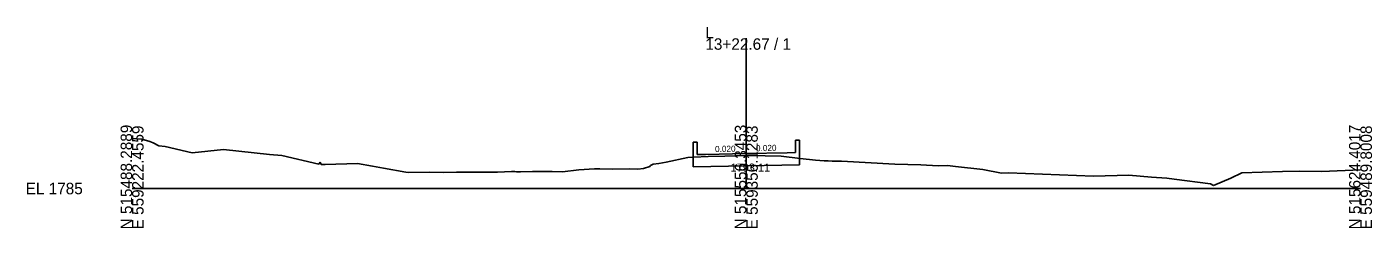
# Model space of a CAD drawing. Extents: x -26 to 1303, y -10 to 9545.
# Drawn here: x -25.7 to 302.8, y 8490.3 to 8539.5 of the extents above; entities that cross this region are included whole.
import ezdxf

# ---------------------------------------------------------------- set-up
doc = ezdxf.new("R2010")
doc.units = 0
for name, color, linetype in [('Exist Cross Section Cell', 7, 'Continuous'), ('Exist XS Center Line Elevation Label', 7, 'Continuous'), ('Exist XS Ground Line', 7, 'Continuous'), ('Prop XS Bridge', 7, 'Continuous'), ('Prop XS Dump Level', 7, 'Continuous'), ('Prop XS SE Text', 7, 'Continuous')]:
    doc.layers.add(name, color=color, linetype=linetype)

msp = doc.modelspace()

# ---------------------------------------------------------------- linework, layer by layer
at = {"layer": 'Exist Cross Section Cell'}
for p, q in [((150, 8500), (150, 8536.74)), ((0, 8500), (150, 8500)), ((150, 8500), (300, 8500))]:
    msp.add_line(p, q, dxfattribs=at)
at = {"layer": 'Exist XS Ground Line'}
for p, q in [((0, 8512.25), (2.41, 8512.03)), ((2.41, 8512.03), (4.35, 8511.48)), ((4.35, 8511.48), (5.13, 8511.21)), ((5.13, 8511.21), (6.55, 8510.43)), ((6.55, 8510.43), (8.05, 8510.29)), ((8.05, 8510.29), (14.68, 8508.74)), ((14.68, 8508.74), (22.32, 8509.58)), ((22.32, 8509.58), (33.55, 8508.35)), ((33.55, 8508.35), (36.54, 8508.07)), ((36.54, 8508.07), (45.58, 8505.94)), ((45.58, 8505.94), (45.93, 8506.47)), ((45.93, 8506.47), (46.2, 8505.85)), ((46.2, 8505.85), (47.14, 8505.87)), ((47.14, 8505.87), (55.06, 8506.08)), ((55.06, 8506.08), (58.68, 8505.44)), ((126.59, 8505.6), (127.27, 8505.94)), ((127.27, 8505.94), (128.66, 8506.15)), ((128.66, 8506.15), (130.46, 8506.41)), ((130.46, 8506.41), (135.7, 8507.58)), ((135.7, 8507.58), (137.21, 8507.69)), ((137.21, 8507.69), (140.72, 8507.79)), ((140.72, 8507.79), (144.78, 8507.89)), ((144.78, 8507.89), (149.88, 8508.11)), ((149.88, 8508.11), (154.62, 8507.99)), ((154.62, 8507.99), (158.51, 8507.88)), ((158.51, 8507.88), (163.14, 8507.36)), ((163.14, 8507.36), (166.87, 8506.97)), ((166.87, 8506.97), (169.01, 8506.76)), ((169.01, 8506.76), (170.01, 8506.77)), ((170.01, 8506.77), (170.95, 8506.7)), ((170.95, 8506.7), (173.23, 8506.7)), ((173.23, 8506.7), (186.27, 8505.98)), ((186.27, 8505.98), (189.48, 8505.84)), ((189.48, 8505.84), (192.63, 8505.81)), ((192.63, 8505.81), (196.87, 8505.55)), ((58.68, 8505.44), (61.38, 8504.95)), ((61.38, 8504.95), (66.86, 8504)), ((66.86, 8504), (67.46, 8503.88)), ((67.46, 8503.88), (72.73, 8504.02)), ((72.73, 8504.02), (76.08, 8503.94)), ((76.08, 8503.94), (79.2, 8504.01)), ((79.2, 8504.01), (80.99, 8503.99)), ((80.99, 8503.99), (88.29, 8503.99)), ((88.29, 8503.99), (89.23, 8503.98)), ((89.23, 8503.98), (92.67, 8504.14)), ((92.67, 8504.14), (93.45, 8504.13)), ((93.45, 8504.13), (93.87, 8504.12)), ((93.87, 8504.12), (94.89, 8504.11)), ((94.89, 8504.11), (97.81, 8504.14)), ((97.81, 8504.14), (102.55, 8504.15)), ((102.55, 8504.15), (105.08, 8504.07)), ((105.08, 8504.07), (109.1, 8504.55)), ((109.1, 8504.55), (112.96, 8504.78)), ((112.96, 8504.78), (114.25, 8504.8)), ((114.25, 8504.8), (117.33, 8504.75)), ((117.33, 8504.75), (121.41, 8504.79)), ((121.41, 8504.79), (123.51, 8504.73)), ((123.51, 8504.73), (124.93, 8504.86)), ((124.93, 8504.86), (126.46, 8505.4)), ((126.46, 8505.4), (126.59, 8505.6)), ((196.87, 8505.55), (199.12, 8505.61)), ((199.12, 8505.61), (201.08, 8505.42)), ((201.08, 8505.42), (207.77, 8504.66)), ((207.77, 8504.66), (212.29, 8503.77)), ((212.29, 8503.77), (214.04, 8503.83)), ((214.04, 8503.83), (234.82, 8503.04)), ((234.82, 8503.04), (243.42, 8503.28)), ((243.42, 8503.28), (249, 8502.8)), ((249, 8502.8), (252.7, 8502.53)), ((252.7, 8502.53), (254.52, 8502.25)), ((264.07, 8500.71), (268.34, 8502.49)), ((268.34, 8502.49), (271.05, 8503.8)), ((271.05, 8503.8), (280.92, 8504.14)), ((280.92, 8504.14), (285.18, 8504.21)), ((285.18, 8504.21), (290.6, 8504.19)), ((290.6, 8504.19), (300, 8504.55)), ((254.52, 8502.25), (263.39, 8501.14)), ((263.39, 8501.14), (264.07, 8500.71))]:
    msp.add_line(p, q, dxfattribs=at)
at = {"layer": 'Prop XS Bridge'}
for p, q in [((137, 8511.32), (137, 8508.32)), ((138, 8511.32), (137, 8511.32)), ((138, 8508.32), (138, 8511.32)), ((162, 8508.8), (162, 8511.8)), ((162, 8511.8), (163, 8511.8)), ((163, 8511.8), (163, 8508.8)), ((137, 8508.32), (137, 8505.32)), ((163, 8505.8), (137, 8505.32)), ((140, 8508.36), (138, 8508.32)), ((140, 8508.36), (150, 8508.56)), ((150, 8508.56), (160, 8508.76)), ((160, 8508.76), (162, 8508.8)), ((163, 8508.8), (163, 8505.8))]:
    msp.add_line(p, q, dxfattribs=at)
at = {"layer": 'Prop XS Dump Level'}
for p, q in [((140, 8508.36), (150, 8508.56)), ((150, 8508.56), (160, 8508.76))]:
    msp.add_line(p, q, dxfattribs=at)

# ---------------------------------------------------------------- texts
at = {"layer": 'Exist Cross Section Cell'}
for s, p in [('L', (140, 8536.74)), ('13+22.67 / 1', (140, 8533.94)), ('EL 1785', (-26, 8498.6))]:
    msp.add_text(s, height=2.8, dxfattribs=at).set_placement(p)
for s, p in [('N 515488.2889', (0, 8490)), ('E 559222.4559', (2.8, 8490)), ('N 515556.3453', (150, 8490)), ('E 559356.1283', (152.8, 8490)), ('N 515624.4017', (300, 8490)), ('E 559489.8008', (302.8, 8490))]:
    msp.add_text(s, height=2.8, rotation=90, dxfattribs=at).set_placement(p)
at = {"layer": 'Exist XS Center Line Elevation Label'}
msp.add_text('1793.11', height=2, dxfattribs=at).set_placement((146.16, 8504.11))
at = {"layer": 'Prop XS Dump Level'}
msp.add_text('Case1', height=0.04, dxfattribs=at).set_placement((163, 8508.88))
at = {"layer": 'Prop XS SE Text'}
for p in [(142.38, 8508.91), (152.38, 8509.11)]:
    msp.add_text('0.020', height=1.5, rotation=1.1458, dxfattribs=at).set_placement(p)

doc.saveas('drawing.dxf')
